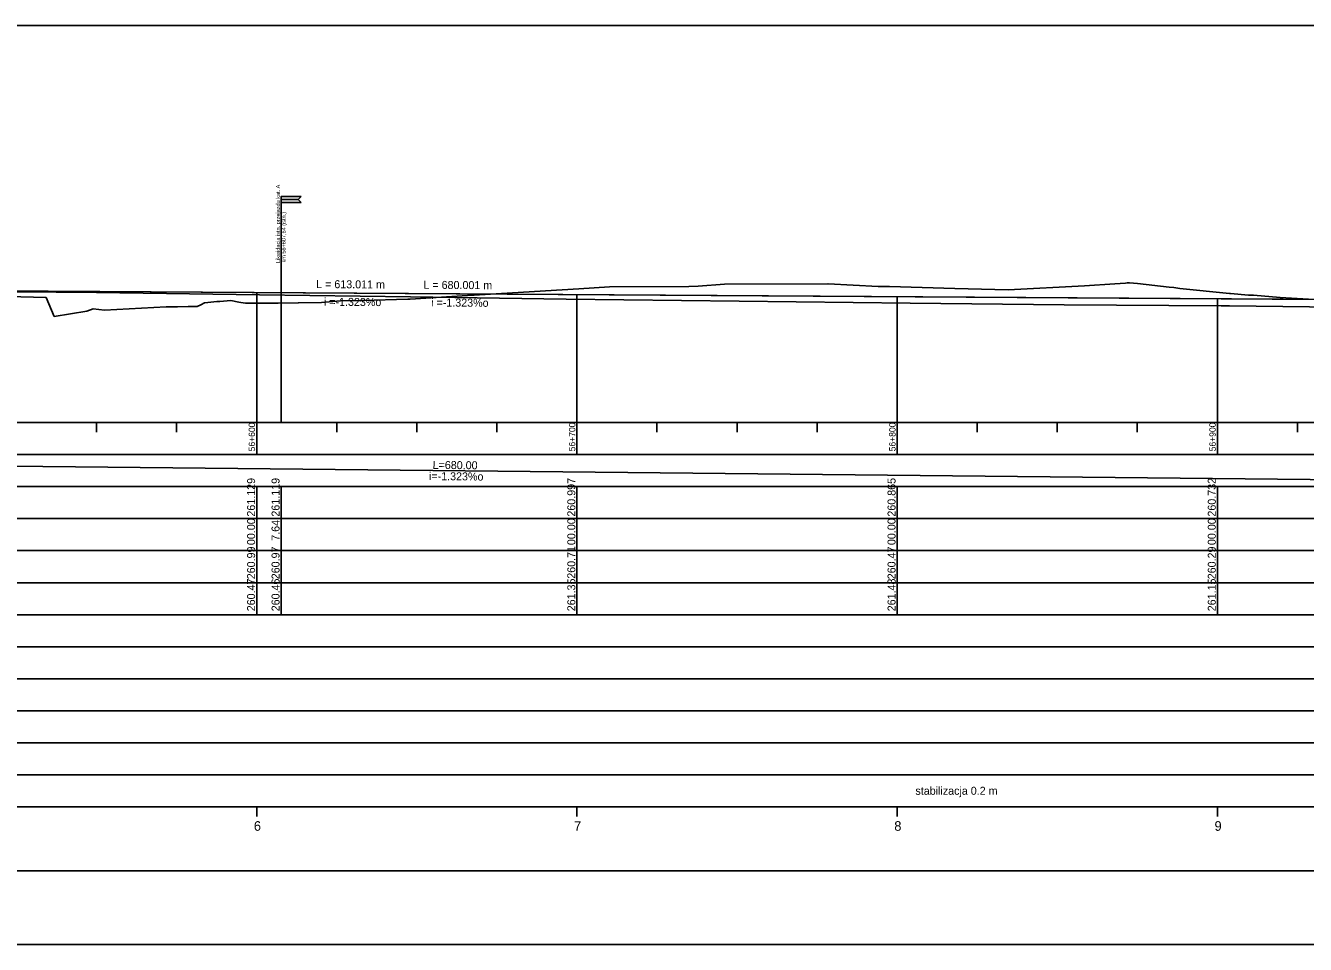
# Model space of a CAD drawing. Extents: x 6445630 to 6518227, y 5499240 to 5511716.
# Drawn here: x 6455759 to 6456158.7, y 5508966.7 to 5509253.7 of the extents above; entities that cross this region are included whole.
import ezdxf

# ---------------------------------------------------------------- set-up
doc = ezdxf.new("R2010")
doc.units = 0
for name, color, linetype in [('Default', 7, 'Continuous'), ('TOR_PROF-obiekty+opisy', 7, 'Continuous'), ('TOR_PROF-opisy pomocnicze', 7, 'Continuous'), ('TOR_PROF-tabelka-geometria T1', 7, 'Continuous'), ('TOR_PROF-tabelka-kilometracja', 7, 'Continuous'), ('TOR_PROF-tabelka-odleglosci T1', 7, 'Continuous'), ('TOR_PROF-tabelka-pochylenia proj T1', 7, 'Continuous'), ('TOR_PROF-tabelka-rodzaj rowu T1', 7, 'Continuous'), ('TOR_PROF-tabelka-rowyT1', 7, 'Continuous'), ('TOR_PROF-tabelka-rurociagi T1', 7, 'Continuous'), ('TOR_PROF-tabelka-rzedne istn T1', 7, 'Continuous'), ('TOR_PROF-tabelka-rzedne proj T1', 7, 'Continuous'), ('TOR_PROF-tabelka-teren istniejacy T1', 7, 'Continuous'), ('TOR_PROF-tabelka-warstwa ochronna T1', 7, 'Continuous'), ('TOR_PROF-tor istniejacy T1', 7, 'Continuous'), ('TOR_PROF-tor projektowany', 7, 'Continuous'), ('TOR_PROF-uklad odniesienia', 7, 'Continuous'), ('TOR_PROF-warstwa ochronna', 7, 'Continuous'), ('TOR_RAMKI-dodatkowe3', 7, 'Continuous'), ('TOR_RAMKI-MASKA WYCIECIA', 7, 'Continuous')]:
    doc.layers.add(name, color=color, linetype=linetype)

msp = doc.modelspace()

# ---------------------------------------------------------------- linework, layer by layer
at = {"layer": 'TOR_PROF-obiekty+opisy'}
msp.add_line((6455838.85, 5509129.74), (6455838.85, 5509200.34), dxfattribs=at)
for points in [[(6455845.1, 5509200.34), (6455844.17, 5509199.4), (6455838.85, 5509199.4), (6455838.85, 5509200.34), (6455845.1, 5509200.34)], [(6455845.1, 5509198.46), (6455844.17, 5509199.4), (6455838.85, 5509199.4), (6455838.85, 5509198.46), (6455845.1, 5509198.46)]]:
    msp.add_lwpolyline(points, dxfattribs=at)
at = {"layer": 'TOR_PROF-tabelka-geometria T1'}
for points in [[(6452331.21, 5508989.74), (6462728.4, 5508989.74)], [(6452331.21, 5508989.74), (6462731.21, 5508989.74)]]:
    msp.add_lwpolyline(points, dxfattribs=at)
at = {"layer": 'TOR_PROF-tabelka-kilometracja'}
for points in [[(6455831.21, 5509006.74), (6455831.21, 5509009.74)], [(6455931.21, 5509006.74), (6455931.21, 5509009.74)], [(6456031.21, 5509006.74), (6456031.21, 5509009.74)], [(6456131.21, 5509006.74), (6456131.21, 5509009.74)]]:
    msp.add_lwpolyline(points, dxfattribs=at)
at = {"layer": 'TOR_PROF-tabelka-odleglosci T1'}
msp.add_lwpolyline([(6452331.21, 5509089.74), (6462731.21, 5509089.74), (6462731.21, 5509099.74), (6452331.21, 5509099.74)], close=True, dxfattribs=at)
for points in [[(6455831.21, 5509089.74), (6455831.21, 5509099.74)], [(6455838.85, 5509089.74), (6455838.85, 5509099.74)], [(6455931.21, 5509089.74), (6455931.21, 5509099.74)], [(6456031.21, 5509089.74), (6456031.21, 5509099.74)], [(6456131.21, 5509089.74), (6456131.21, 5509099.74)]]:
    msp.add_lwpolyline(points, dxfattribs=at)
at = {"layer": 'TOR_PROF-tabelka-pochylenia proj T1'}
msp.add_lwpolyline([(6452331.21, 5509109.74), (6462731.21, 5509109.74), (6462731.21, 5509119.74), (6452331.21, 5509119.74)], close=True, dxfattribs=at)
msp.add_lwpolyline([(6455551.21, 5509118.24), (6456231.21, 5509111.24)], dxfattribs=at)
at = {"layer": 'TOR_PROF-tabelka-rodzaj rowu T1'}
for points in [[(6452331.21, 5509049.74), (6462731.21, 5509049.74), (6462731.21, 5509059.74), (6452331.21, 5509059.74)], [(6452331.21, 5509029.74), (6462731.21, 5509029.74), (6462731.21, 5509039.74), (6452331.21, 5509039.74)]]:
    msp.add_lwpolyline(points, close=True, dxfattribs=at)
at = {"layer": 'TOR_PROF-tabelka-rowyT1'}
msp.add_lwpolyline([(6452331.21, 5509059.74), (6462731.21, 5509059.74), (6462731.21, 5509069.74), (6452331.21, 5509069.74)], close=True, dxfattribs=at)
at = {"layer": 'TOR_PROF-tabelka-rurociagi T1'}
msp.add_lwpolyline([(6452331.21, 5509039.74), (6462731.21, 5509039.74), (6462731.21, 5509049.74), (6452331.21, 5509049.74)], close=True, dxfattribs=at)
at = {"layer": 'TOR_PROF-tabelka-rzedne istn T1'}
msp.add_lwpolyline([(6452331.21, 5509079.74), (6462731.21, 5509079.74), (6462731.21, 5509089.74), (6452331.21, 5509089.74)], close=True, dxfattribs=at)
for points in [[(6455831.21, 5509079.74), (6455831.21, 5509089.74)], [(6455838.85, 5509079.74), (6455838.85, 5509089.74)], [(6455931.21, 5509079.74), (6455931.21, 5509089.74)], [(6456031.21, 5509079.74), (6456031.21, 5509089.74)], [(6456131.21, 5509079.74), (6456131.21, 5509089.74)], [(6455831.21, 5509069.74), (6455831.21, 5509079.74)], [(6455831.21, 5509069.74), (6455831.21, 5509079.74)], [(6455831.21, 5509069.74), (6455831.21, 5509079.74)], [(6455831.21, 5509069.74), (6455831.21, 5509079.74)], [(6455831.21, 5509069.74), (6455831.21, 5509079.74)], [(6455838.85, 5509069.74), (6455838.85, 5509079.74)], [(6455931.21, 5509069.74), (6455931.21, 5509079.74)], [(6455931.21, 5509069.74), (6455931.21, 5509079.74)], [(6455931.21, 5509069.74), (6455931.21, 5509079.74)], [(6455931.21, 5509069.74), (6455931.21, 5509079.74)], [(6455931.21, 5509069.74), (6455931.21, 5509079.74)], [(6456031.21, 5509069.74), (6456031.21, 5509079.74)], [(6456031.21, 5509069.74), (6456031.21, 5509079.74)], [(6456031.21, 5509069.74), (6456031.21, 5509079.74)], [(6456031.21, 5509069.74), (6456031.21, 5509079.74)], [(6456031.21, 5509069.74), (6456031.21, 5509079.74)], [(6456131.21, 5509069.74), (6456131.21, 5509079.74)], [(6456131.21, 5509069.74), (6456131.21, 5509079.74)], [(6456131.21, 5509069.74), (6456131.21, 5509079.74)], [(6456131.21, 5509069.74), (6456131.21, 5509079.74)], [(6456131.21, 5509069.74), (6456131.21, 5509079.74)]]:
    msp.add_lwpolyline(points, dxfattribs=at)
at = {"layer": 'TOR_PROF-tabelka-rzedne proj T1'}
msp.add_lwpolyline([(6452331.21, 5509099.74), (6462731.21, 5509099.74), (6462731.21, 5509109.74), (6452331.21, 5509109.74)], close=True, dxfattribs=at)
for points in [[(6455831.21, 5509099.74), (6455831.21, 5509109.74)], [(6455838.85, 5509099.74), (6455838.85, 5509109.74)], [(6455931.21, 5509099.74), (6455931.21, 5509109.74)], [(6456031.21, 5509099.74), (6456031.21, 5509109.74)], [(6456131.21, 5509099.74), (6456131.21, 5509109.74)]]:
    msp.add_lwpolyline(points, dxfattribs=at)
at = {"layer": 'TOR_PROF-tabelka-teren istniejacy T1'}
msp.add_lwpolyline([(6452331.21, 5509069.74), (6462731.21, 5509069.74), (6462731.21, 5509079.74), (6452331.21, 5509079.74)], close=True, dxfattribs=at)
msp.add_lwpolyline([(6452331.21, 5509069.74), (6462731.21, 5509069.74), (6462731.21, 5509079.74), (6452331.21, 5509079.74)], close=True, dxfattribs=at)
msp.add_lwpolyline([(6452331.21, 5509069.74), (6462731.21, 5509069.74), (6462731.21, 5509079.74), (6452331.21, 5509079.74)], close=True, dxfattribs=at)
msp.add_lwpolyline([(6452331.21, 5509069.74), (6462731.21, 5509069.74), (6462731.21, 5509079.74), (6452331.21, 5509079.74)], close=True, dxfattribs=at)
msp.add_lwpolyline([(6452331.21, 5509069.74), (6462731.21, 5509069.74), (6462731.21, 5509079.74), (6452331.21, 5509079.74)], close=True, dxfattribs=at)
at = {"layer": 'TOR_PROF-tabelka-warstwa ochronna T1'}
msp.add_lwpolyline([(6452331.21, 5509019.74), (6462731.21, 5509019.74), (6462731.21, 5509029.74), (6452331.21, 5509029.74)], close=True, dxfattribs=at)
at = {"layer": 'TOR_PROF-tor istniejacy T1'}
msp.add_lwpolyline([(6456580.72, 5509162.29), (6456529.85, 5509162.44), (6456479.54, 5509162.79), (6456431.21, 5509163.29), (6456379.3, 5509163.69), (6456328.9, 5509164.19), (6456281.17, 5509164.64), (6456233.54, 5509165.19), (6456191.17, 5509165.58), (6456181.17, 5509165.69), (6456176.61, 5509165.74), (6456135.02, 5509166.19), (6456132.4, 5509166.19), (6456083.4, 5509166.54), (6456035.29, 5509167.04), (6455981.91, 5509167.69), (6455927.89, 5509168.34), (6455879.29, 5509168.99), (6455832.07, 5509169.69), (6455781.2, 5509170.34), (6455730.52, 5509170.84)], dxfattribs=at)
at = {"layer": 'TOR_PROF-tor projektowany'}
for q in [(6456164.22, 5509168.18), (6456231.21, 5509167.74)]:
    msp.add_line((6455551.21, 5509172.24), q, dxfattribs=at)
for points in [[(6455831.21, 5509170.38), (6455831.21, 5509134.74), (6455831.21, 5509129.74), (6455831.21, 5509129.74)], [(6455831.21, 5509170.38), (6455831.21, 5509134.74), (6455831.21, 5509129.74), (6455831.21, 5509129.74)], [(6455931.21, 5509169.72), (6455931.21, 5509134.74), (6455931.21, 5509129.74), (6455931.21, 5509129.74)], [(6455931.21, 5509169.72), (6455931.21, 5509134.74), (6455931.21, 5509129.74), (6455931.21, 5509129.74)], [(6456031.21, 5509169.06), (6456031.21, 5509134.74), (6456031.21, 5509129.74), (6456031.21, 5509129.74)], [(6456031.21, 5509169.06), (6456031.21, 5509134.74), (6456031.21, 5509129.74), (6456031.21, 5509129.74)], [(6456131.21, 5509168.4), (6456131.21, 5509134.74), (6456131.21, 5509129.74), (6456131.21, 5509129.74)], [(6456131.21, 5509168.4), (6456131.21, 5509134.74), (6456131.21, 5509129.74), (6456131.21, 5509129.74)]]:
    msp.add_lwpolyline(points, dxfattribs=at)
at = {"layer": 'TOR_PROF-uklad odniesienia'}
for p, q in [((6452331.21, 5509129.74), (6462731.21, 5509129.74)), ((6455781.21, 5509126.74), (6455781.21, 5509129.74)), ((6455806.21, 5509126.74), (6455806.21, 5509129.74)), ((6455831.21, 5509119.74), (6455831.21, 5509129.74)), ((6455856.21, 5509126.74), (6455856.21, 5509129.74)), ((6455881.21, 5509126.74), (6455881.21, 5509129.74)), ((6455906.21, 5509126.74), (6455906.21, 5509129.74)), ((6455931.21, 5509119.74), (6455931.21, 5509129.74)), ((6455956.21, 5509126.74), (6455956.21, 5509129.74)), ((6455981.21, 5509126.74), (6455981.21, 5509129.74)), ((6456006.21, 5509126.74), (6456006.21, 5509129.74)), ((6456031.21, 5509119.74), (6456031.21, 5509129.74)), ((6456056.21, 5509126.74), (6456056.21, 5509129.74)), ((6456081.21, 5509126.74), (6456081.21, 5509129.74)), ((6456106.21, 5509126.74), (6456106.21, 5509129.74)), ((6456131.21, 5509119.74), (6456131.21, 5509129.74)), ((6456156.21, 5509126.74), (6456156.21, 5509129.74))]:
    msp.add_line(p, q, dxfattribs=at)
at = {"layer": 'TOR_PROF-warstwa ochronna'}
msp.add_lwpolyline([(6452331.21, 5509009.74), (6462731.21, 5509009.74), (6462731.21, 5509019.74), (6452331.21, 5509019.74)], close=True, dxfattribs=at)
at = {"layer": 'TOR_RAMKI-dodatkowe3'}
for p, q in [((6455921.41, 5509170.88), (6455931.81, 5509171.51)), ((6455931.81, 5509171.51), (6455941.37, 5509172.19)), ((6455941.37, 5509172.19), (6455966.16, 5509172.29)), ((6455966.16, 5509172.29), (6455969.08, 5509172.32)), ((6455969.08, 5509172.32), (6455977.3, 5509173.03)), ((6455977.3, 5509173.03), (6456009.58, 5509173.04)), ((6456009.58, 5509173.04), (6456009.72, 5509173.04)), ((6456009.72, 5509173.04), (6456025.26, 5509172.27)), ((6456025.26, 5509172.27), (6456028.85, 5509172.22)), ((6456028.85, 5509172.22), (6456049.25, 5509171.66)), ((6456049.25, 5509171.66), (6456053.43, 5509171.53)), ((6456053.43, 5509171.53), (6456065.91, 5509171.18)), ((6456065.91, 5509171.18), (6456089.72, 5509172.51)), ((6456089.72, 5509172.51), (6456099.18, 5509173.05)), ((6456099.18, 5509173.05), (6456102.55, 5509173.31)), ((6456102.55, 5509173.31), (6456103.01, 5509173.35)), ((6456103.01, 5509173.35), (6456103.62, 5509173.43)), ((6456103.62, 5509173.43), (6456103.75, 5509173.44)), ((6456103.75, 5509173.44), (6456106.26, 5509173.16)), ((6456106.26, 5509173.16), (6456116.2, 5509172.01)), ((6456116.2, 5509172.01), (6456117.65, 5509171.89)), ((6456117.65, 5509171.89), (6456119.53, 5509171.63)), ((6456119.53, 5509171.63), (6456134.99, 5509170.09)), ((6455753.59, 5509169.12), (6455765.48, 5509168.78)), ((6455765.48, 5509168.78), (6455768, 5509162.9)), ((6455813.75, 5509166.53), (6455814.93, 5509167.11)), ((6455814.93, 5509167.11), (6455814.97, 5509167.13)), ((6455814.97, 5509167.13), (6455815.03, 5509167.17)), ((6455815.03, 5509167.17), (6455818.74, 5509167.61)), ((6455818.74, 5509167.61), (6455819.7, 5509167.6)), ((6455819.7, 5509167.6), (6455823.18, 5509167.91)), ((6455823.18, 5509167.91), (6455825.6, 5509167.37)), ((6455825.6, 5509167.37), (6455826.27, 5509167.27)), ((6455826.27, 5509167.27), (6455827.69, 5509167.08)), ((6455827.69, 5509167.08), (6455837.72, 5509167.09)), ((6455837.72, 5509167.09), (6455837.94, 5509167.03)), ((6455837.94, 5509167.03), (6455844.2, 5509167.17)), ((6455844.2, 5509167.17), (6455844.27, 5509167.17)), ((6455844.27, 5509167.17), (6455851.45, 5509167.24)), ((6455851.45, 5509167.24), (6455857.36, 5509167.82)), ((6455857.36, 5509167.82), (6455861.89, 5509167.84)), ((6455861.89, 5509167.84), (6455863.6, 5509167.8)), ((6455863.6, 5509167.8), (6455863.8, 5509167.83)), ((6455863.8, 5509167.83), (6455864.4, 5509167.83)), ((6455864.4, 5509167.83), (6455878.4, 5509168.26)), ((6455878.4, 5509168.26), (6455879.13, 5509168.31)), ((6455879.13, 5509168.31), (6455896.99, 5509169.42)), ((6455896.99, 5509169.42), (6455899.11, 5509169.55)), ((6455899.11, 5509169.55), (6455921.41, 5509170.88)), ((6456134.99, 5509170.09), (6456135.36, 5509170.06)), ((6456135.36, 5509170.06), (6456140.93, 5509169.58)), ((6456140.93, 5509169.58), (6456142.52, 5509169.53)), ((6456142.52, 5509169.53), (6456150.8, 5509168.77)), ((6456150.8, 5509168.77), (6456161.43, 5509168.15)), ((6455768, 5509162.9), (6455778.18, 5509164.51)), ((6455778.18, 5509164.51), (6455780.15, 5509165.23)), ((6455780.15, 5509165.23), (6455783.68, 5509164.89)), ((6455783.68, 5509164.89), (6455802.99, 5509165.86)), ((6455802.99, 5509165.86), (6455806.48, 5509165.95)), ((6455806.48, 5509165.95), (6455809.76, 5509166.05)), ((6455809.76, 5509166.05), (6455812.62, 5509166.02)), ((6455812.62, 5509166.02), (6455813.75, 5509166.53))]:
    msp.add_line(p, q, dxfattribs=at)
at = {"layer": 'TOR_RAMKI-MASKA WYCIECIA'}
msp.add_lwpolyline([(6454268.59, 5508966.75), (6456248.59, 5508966.75), (6456248.59, 5509253.75), (6454268.59, 5509253.75)], close=True, dxfattribs=at)

# ---------------------------------------------------------------- texts
at = {"layer": 'Default'}
for p in [(6455781.2, 5509170.34), (6455832.07, 5509169.69), (6455879.29, 5509168.99), (6455927.89, 5509168.34), (6455981.91, 5509167.69), (6456035.29, 5509167.04), (6456083.4, 5509166.54), (6456132.4, 5509166.19), (6456135.02, 5509166.19)]:
    msp.add_text('+', height=0.001, dxfattribs=at).set_placement(p)
at = {"layer": 'TOR_PROF-obiekty+opisy'}
for s, p in [('Likwidacja istn. przejazdu kat. A', (6455838.48, 5509179.59)), ('km 56+607,64 (istn.) ', (6455840.27, 5509179.75))]:
    msp.add_text(s, height=1.25, rotation=90, dxfattribs=at).set_placement(p)
at = {"layer": 'TOR_PROF-opisy pomocnicze'}
for s, p in [('L = 613.011 m', (6455849.78, 5509171.76)), ('L = 680.001 m', (6455883.28, 5509171.54)), ('  i =-1.323%o', (6455850.33, 5509166.26)), ('  i =-1.323%o', (6455883.83, 5509166.03))]:
    msp.add_text(s, height=2.5, rotation=359.6209, dxfattribs=at).set_placement(p)
at = {"layer": 'TOR_PROF-tabelka-kilometracja'}
for s, p in [('6', (6455830.32, 5509002.24)), ('7', (6455930.32, 5509002.24)), ('8', (6456030.32, 5509002.24)), ('9', (6456130.32, 5509002.24))]:
    msp.add_text(s, height=3, dxfattribs=at).set_placement(p)
at = {"layer": 'TOR_PROF-tabelka-odleglosci T1'}
for s, p in [('00.00', (6455830.71, 5509091.48)), ('7.64', (6455838.35, 5509092.84)), ('00.00', (6455930.71, 5509091.48)), ('00.00', (6456030.71, 5509091.48)), ('00.00', (6456130.71, 5509091.48))]:
    msp.add_text(s, height=2.5, rotation=90, dxfattribs=at).set_placement(p)
at = {"layer": 'TOR_PROF-tabelka-pochylenia proj T1'}
for s, p in [('L=680.00', (6455886.14, 5509115.29)), ('i=-1.323%o', (6455885, 5509111.8))]:
    msp.add_text(s, height=2.5, rotation=359.4102, dxfattribs=at).set_placement(p)
at = {"layer": 'TOR_PROF-tabelka-rzedne istn T1'}
for s, p in [('260.99', (6455830.71, 5509080.8)), ('260.97', (6455838.35, 5509080.8)), ('260.71', (6455930.71, 5509080.97)), ('260.47', (6456030.71, 5509080.8)), ('260.29', (6456130.71, 5509080.8)), ('260.47', (6455830.71, 5509070.8)), ('260.46', (6455838.35, 5509070.8)), ('261.35', (6455930.71, 5509070.8)), ('261.48', (6456030.71, 5509070.8)), ('261.15', (6456130.71, 5509070.8))]:
    msp.add_text(s, height=2.5, rotation=90, dxfattribs=at).set_placement(p)
at = {"layer": 'TOR_PROF-tabelka-rzedne proj T1'}
for s, p in [('261.129', (6455830.71, 5509100.37)), ('261.119', (6455838.35, 5509100.37)), ('260.997', (6455930.71, 5509100.37)), ('260.865', (6456030.71, 5509100.37)), ('260.732', (6456130.71, 5509100.38))]:
    msp.add_text(s, height=2.5, rotation=90, dxfattribs=at).set_placement(p)
at = {"layer": 'TOR_PROF-uklad odniesienia'}
for s, p in [('56+600', (6455830.71, 5509120.76)), ('56+700', (6455930.71, 5509120.76)), ('56+800', (6456030.71, 5509120.76)), ('56+900', (6456130.71, 5509120.76))]:
    msp.add_text(s, height=2, rotation=90, dxfattribs=at).set_placement(p)
at = {"layer": 'TOR_PROF-warstwa ochronna'}
msp.add_text('stabilizacja 0.2 m', height=2.5, dxfattribs=at).set_placement((6456036.92, 5509013.49))

doc.saveas('drawing.dxf')
